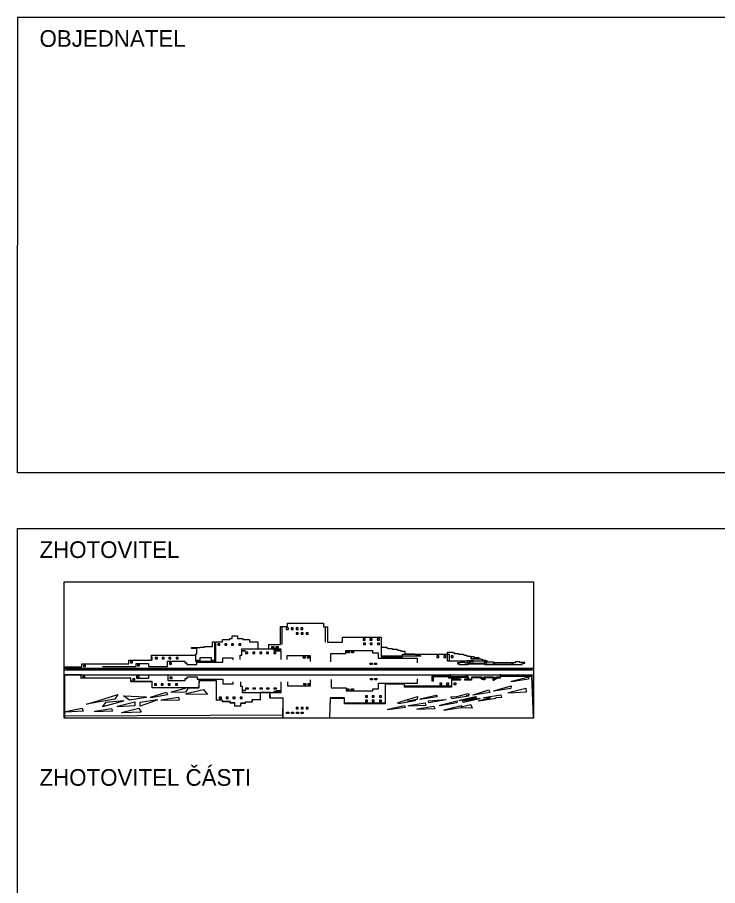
# Model space of a CAD drawing. Extents: x -740053 to -737517, y -1033516 to -1032465.
# Drawn here: x -738163 to -738131.47, y -1032574.53 to -1032535.46 of the extents above; entities that cross this region are included whole.
import ezdxf

# ---------------------------------------------------------------- set-up
doc = ezdxf.new("R2010")
doc.units = 0
doc.layers.add('promika-rozp', color=7, linetype='Continuous')

# ---------------------------------------------------------------- blocks, each defined once
blk = doc.blocks.new('onegast')
for p, q in [((22.998, 7.759), (22.998, 9.646)), ((27.598, 8.019), (27.598, 9.571)), ((9.252, 6.105), (9.252, 6.463)), ((9.309, 6.102), (9.309, 6.46)), ((6.825, 5.723), (6.825, 6.082)), ((0.046, 5.264), (49.513, 5.263)), ((0.046, 5.075), (49.427, 5.075)), ((0.278, 5.186), (49.435, 5.186)), ((0.046, 4.561), (49.435, 4.561))]:
    blk.add_line(p, q)
for points in [[(0, 14.352), (49.53, 14.352), (49.53, 0), (0, 0)], [(23.451, 9.351), (23.667, 9.351), (23.667, 9.502), (23.451, 9.502)], [(23.957, 9.351), (24.173, 9.351), (24.173, 9.502), (23.957, 9.502)], [(24.48, 9.351), (24.696, 9.351), (24.696, 9.502), (24.48, 9.502)], [(24.994, 9.351), (25.21, 9.351), (25.21, 9.502), (24.994, 9.502)], [(24.501, 8.843), (24.717, 8.843), (24.717, 8.994), (24.501, 8.994)], [(25.007, 8.843), (25.223, 8.843), (25.223, 8.994), (25.007, 8.994)], [(25.53, 8.843), (25.746, 8.843), (25.746, 8.994), (25.53, 8.994)], [(21.914, 7.53), (22.13, 7.53), (22.13, 7.378), (21.914, 7.378)], [(22.377, 7.53), (22.593, 7.53), (22.593, 7.378), (22.377, 7.378)], [(19.161, 6.799), (19.377, 6.799), (19.377, 6.95), (19.161, 6.95)], [(25.216, 6.462), (25.432, 6.462), (25.432, 6.311), (25.216, 6.311)], [(25.679, 6.462), (25.895, 6.462), (25.895, 6.311), (25.679, 6.311)], [(29.857, 7.022), (30.073, 7.022), (30.073, 6.871), (29.857, 6.871)], [(30.32, 7.022), (30.536, 7.022), (30.536, 6.871), (30.32, 6.871)], [(32.298, 5.793), (32.514, 5.793), (32.514, 5.642), (32.298, 5.642)], [(32.761, 5.793), (32.977, 5.793), (32.977, 5.642), (32.761, 5.642)], [(32.333, 4.18), (32.549, 4.18), (32.549, 4.029), (32.333, 4.029)], [(32.796, 4.18), (33.012, 4.18), (33.012, 4.029), (32.796, 4.029)], [(12.874, 2.574), (14.701, 3.028), (15.132, 2.483), (12.879, 2.512)], [(19.195, 3.182), (19.411, 3.182), (19.411, 3.031), (19.195, 3.031)], [(25.286, 3.656), (25.502, 3.656), (25.502, 3.505), (25.286, 3.505)], [(25.749, 3.656), (25.965, 3.656), (25.965, 3.505), (25.749, 3.505)], [(29.843, 3.074), (30.059, 3.074), (30.059, 2.923), (29.843, 2.923)], [(30.306, 3.074), (30.522, 3.074), (30.522, 2.923), (30.306, 2.923)], [(3.464, 1.792), (5.689, 2.483), (5.353, 1.985), (2.388, 1.451)], [(4.449, 1.687), (6.263, 1.842), (6.277, 1.778), (4.06, 1.174)], [(6.257, 2.359), (8.663, 2.239), (8.678, 2.175), (6.892, 1.886)], [(8.049, 1.674), (9.825, 1.965), (9.84, 1.9), (8.039, 1.247)], [(9.139, 2.21), (10.813, 2.729), (10.929, 2.436), (9.143, 2.148)], [(10.285, 1.911), (12.061, 2.202), (12.15, 1.899), (10.289, 1.849)], [(0.161, 0.692), (1.912, 1.059), (2.012, 0.718), (0.165, 0.63)], [(3.24, 0.71), (5.016, 1), (5.119, 0.715), (3.244, 0.648)], [(5.644, 1.239), (7.471, 1.693), (7.457, 1.283), (5.649, 1.176)], [(6.077, 0.602), (7.903, 1.057), (8.126, 0.622), (6.081, 0.54)], [(24.501, 0.974), (24.717, 0.974), (24.717, 1.125), (24.501, 1.125)], [(25.007, 0.974), (25.223, 0.974), (25.223, 1.125), (25.007, 1.125)], [(25.53, 0.974), (25.746, 0.974), (25.746, 1.125), (25.53, 1.125)], [(23.485, 0.631), (23.701, 0.631), (23.701, 0.48), (23.485, 0.48)], [(23.99, 0.631), (24.206, 0.631), (24.206, 0.48), (23.99, 0.48)], [(24.513, 0.631), (24.729, 0.631), (24.729, 0.48), (24.513, 0.48)], [(25.028, 0.631), (25.244, 0.631), (25.244, 0.48), (25.028, 0.48)]]:
    blk.add_lwpolyline(points, close=True)
for points in [[(0.046, 5.405), (1.862, 5.405), (1.862, 5.731), (6.84, 5.731), (6.84, 6.109), (9.238, 6.109), (9.238, 6.643), (13.878, 6.643), (13.878, 6.005), (16.015, 6.005), (16.015, 8.023), (16.706, 8.023), (16.706, 8.284), (17.475, 8.284), (17.475, 8.401), (17.749, 8.401), (17.749, 8.662), (18.296, 8.662), (18.296, 8.388), (18.879, 8.388), (18.879, 8.272), (19.556, 8.272), (19.556, 8.037), (20.443, 8.037), (20.443, 7.282), (21.616, 7.282), (21.616, 7.764), (22.841, 7.764), (22.841, 9.665), (23.57, 9.665), (23.57, 9.994), (27.389, 9.994), (27.389, 9.629), (27.806, 9.629), (27.806, 8.014), (29.37, 8.014), (29.37, 8.522), (33.462, 8.522), (33.462, 6.412), (35.707, 6.412), (35.707, 6.737), (40.62, 6.737), (40.62, 6.034), (44.351, 6.034), (44.351, 5.656), (48.313, 5.656)], [(31.563, 8.207), (31.779, 8.207), (31.779, 8.358), (31.563, 8.358), (31.563, 8.207)], [(32.276, 8.207), (32.493, 8.207), (32.493, 8.358), (32.276, 8.358), (32.276, 8.207)], [(33.049, 8.207), (33.265, 8.207), (33.265, 8.358), (33.049, 8.358), (33.049, 8.207)], [(14.328, 6.074), (13.905, 6.074), (13.905, 6.765), (14, 6.765), (14, 7.326), (13.453, 7.326), (13.453, 7.425), (14.378, 7.425), (14.378, 7.475), (14.825, 7.475), (14.825, 7.544), (15.233, 7.544), (15.273, 7.544), (15.68, 7.544), (15.68, 8.021), (15.879, 8.021), (15.879, 6.074), (15.571, 6.074), (15.571, 6.362), (14.328, 6.362), (14.328, 6.074)], [(16.228, 7.685), (16.444, 7.685), (16.444, 7.836), (16.228, 7.836), (16.228, 7.685)], [(16.952, 7.685), (17.168, 7.685), (17.168, 7.836), (16.952, 7.836), (16.952, 7.685)], [(17.666, 7.685), (17.882, 7.685), (17.882, 7.836), (17.666, 7.836), (17.666, 7.685)], [(18.439, 7.685), (18.655, 7.685), (18.655, 7.836), (18.439, 7.836), (18.439, 7.685)], [(31.581, 7.761), (31.797, 7.761), (31.797, 7.913), (31.581, 7.913), (31.581, 7.761)], [(32.295, 7.761), (32.511, 7.761), (32.511, 7.913), (32.295, 7.913), (32.295, 7.761)], [(33.067, 7.761), (33.284, 7.761), (33.284, 7.913), (33.067, 7.913), (33.067, 7.761)], [(37.637, 6.532), (33.482, 6.532), (33.482, 7.473), (34.037, 7.473), (34.037, 7.386), (34.193, 7.386), (34.193, 7.317), (34.616, 7.317), (34.616, 7.275), (35.159, 7.275), (35.159, 7.197), (35.257, 7.197), (35.257, 7.144), (35.467, 7.144), (35.467, 7.095), (35.652, 7.095), (35.652, 7.062), (35.94, 7.062), (35.94, 6.779), (36.976, 6.779), (36.976, 6.725), (37.165, 6.725), (37.165, 6.639), (37.502, 6.639), (37.502, 6.565), (37.637, 6.565), (37.637, 6.532)], [(18.576, 6.169), (18.576, 6.617), (18.746, 6.617), (18.746, 7.081), (19.149, 7.081), (19.149, 7.081), (18.746, 7.081), (18.746, 7.282), (22.862, 7.282), (22.862, 7.282), (22.862, 7.183), (22.396, 7.183), (22.396, 7.088), (22.871, 7.088), (22.871, 6.157)], [(19.919, 6.799), (20.135, 6.799), (20.135, 6.95), (19.919, 6.95), (19.919, 6.799)], [(20.644, 6.799), (20.86, 6.799), (20.86, 6.95), (20.644, 6.95), (20.644, 6.799)], [(21.358, 6.799), (21.574, 6.799), (21.574, 6.95), (21.358, 6.95), (21.358, 6.799)], [(22.13, 6.799), (22.346, 6.799), (22.346, 6.95), (22.13, 6.95), (22.13, 6.799)], [(22.141, 7.131), (22.357, 7.131), (22.357, 7.282), (22.141, 7.282), (22.141, 7.131)], [(23.534, 6.16), (23.534, 6.579), (25.98, 6.579), (25.98, 5.951)], [(28.148, 5.929), (28.148, 6.792), (28.724, 6.792), (28.724, 6.792), (29.741, 6.792), (29.741, 7.118), (30.144, 7.118), (30.144, 7.118), (30.97, 7.118), (30.97, 7.118), (32.543, 7.118), (32.543, 6.888), (33.138, 6.888), (33.138, 6.313), (37.246, 6.313), (37.246, 5.833)], [(39.341, 6.398), (39.557, 6.398), (39.557, 6.549), (39.341, 6.549), (39.341, 6.398)], [(40.055, 6.398), (40.271, 6.398), (40.271, 6.549), (40.055, 6.549), (40.055, 6.398)], [(40.466, 6.007), (40.466, 6.948), (41.021, 6.948), (41.021, 6.861), (41.177, 6.861), (41.177, 6.792), (41.6, 6.792), (41.6, 6.75), (42.143, 6.75), (42.143, 6.672), (42.241, 6.672), (42.241, 6.619), (42.451, 6.619), (42.451, 6.57), (42.636, 6.57), (42.636, 6.537), (42.924, 6.537), (42.924, 6.254), (43.96, 6.254), (43.96, 6.2), (44.149, 6.2), (44.149, 6.114), (44.486, 6.114), (44.486, 6.04), (44.622, 6.04), (44.622, 6.007), (40.466, 6.007)], [(44.622, 6.007), (40.466, 6.007), (40.466, 6.948), (41.021, 6.948), (41.021, 6.861), (41.177, 6.861), (41.177, 6.792), (41.6, 6.792), (41.6, 6.75), (42.143, 6.75), (42.143, 6.672), (42.241, 6.672), (42.241, 6.619), (42.451, 6.619), (42.451, 6.57), (42.636, 6.57), (42.636, 6.537), (42.924, 6.537), (42.924, 6.254), (43.96, 6.254), (43.96, 6.2), (44.149, 6.2), (44.149, 6.114), (44.486, 6.114), (44.486, 6.04), (44.622, 6.04), (44.622, 6.007)], [(40.827, 6.398), (41.043, 6.398), (41.043, 6.549), (40.827, 6.549), (40.827, 6.398)], [(42.958, 6.466), (42.958, 6.276), (43.791, 6.276), (43.791, 6.348), (43.516, 6.348), (43.516, 6.365), (43.342, 6.365), (43.342, 6.413), (43.192, 6.413), (43.192, 6.466), (42.958, 6.466)], [(43.192, 6.466), (42.958, 6.466), (42.958, 6.276), (43.791, 6.276), (43.791, 6.348), (43.516, 6.348), (43.516, 6.365), (43.342, 6.365), (43.342, 6.413), (43.192, 6.413), (43.192, 6.466)], [(2.06, 5.439), (2.276, 5.439), (2.276, 5.591), (2.06, 5.591), (2.06, 5.439)], [(4.051, 5.42), (7.596, 5.42), (7.596, 5.765), (8.897, 5.765), (8.897, 5.42), (10.933, 5.42), (10.933, 6.01), (12.761, 6.01), (12.761, 5.826), (12.957, 5.826), (12.957, 5.643), (14, 5.643), (14, 5.888), (16.736, 5.888), (16.736, 6.366), (17.815, 6.366), (17.815, 6.145)], [(7.024, 5.813), (7.24, 5.813), (7.24, 5.964), (7.024, 5.964), (7.024, 5.813)], [(7.749, 5.505), (7.965, 5.505), (7.965, 5.656), (7.749, 5.656), (7.749, 5.505)], [(9.628, 6.243), (9.844, 6.243), (9.844, 6.394), (9.628, 6.394), (9.628, 6.243)], [(10.353, 6.243), (10.569, 6.243), (10.569, 6.394), (10.353, 6.394), (10.353, 6.243)], [(11.067, 6.243), (11.283, 6.243), (11.283, 6.394), (11.067, 6.394), (11.067, 6.243)], [(11.131, 5.681), (11.348, 5.681), (11.348, 5.832), (11.131, 5.832), (11.131, 5.681)], [(11.839, 6.243), (12.055, 6.243), (12.055, 6.394), (11.839, 6.394), (11.839, 6.243)], [(41.512, 5.831), (41.512, 5.707), (41.669, 5.707), (41.669, 5.636), (42.598, 5.636), (42.598, 5.694), (42.709, 5.694), (42.709, 5.727), (44.282, 5.727), (44.282, 5.811), (44.431, 5.811), (44.431, 5.844), (44.516, 5.844), (44.516, 5.681), (45.309, 5.681), (45.309, 5.74), (45.433, 5.74), (45.433, 5.779), (45.491, 5.779), (45.491, 5.805), (47.253, 5.805), (47.253, 5.707), (47.396, 5.707), (47.396, 5.649), (48.254, 5.649), (48.254, 5.727), (48.443, 5.727), (48.443, 5.785), (48.599, 5.785), (48.599, 5.87), (48.098, 5.87), (48.098, 5.922), (47.578, 5.922), (47.578, 5.831), (45.335, 5.831), (45.335, 5.902), (44.425, 5.902), (44.425, 5.772), (44.282, 5.772), (44.282, 5.746), (42.702, 5.746), (42.702, 5.811), (42.826, 5.811), (42.826, 5.967), (43.196, 5.967), (43.196, 6.019), (42.546, 6.019), (42.546, 5.863), (42.683, 5.863), (42.683, 5.798), (42.332, 5.798), (42.332, 5.87), (41.838, 5.87), (41.838, 5.824), (41.512, 5.831)], [(44.282, 5.727), (44.282, 5.746), (42.702, 5.746), (42.702, 5.811), (42.826, 5.811), (42.826, 5.967), (43.196, 5.967), (43.196, 6.019), (42.546, 6.019), (42.546, 5.863), (42.683, 5.863), (42.683, 5.798), (42.332, 5.798), (42.332, 5.87), (41.838, 5.87), (41.838, 5.824), (41.512, 5.831), (41.512, 5.707), (41.669, 5.707), (41.669, 5.636), (42.598, 5.636), (42.598, 5.694), (42.709, 5.694), (42.709, 5.727), (44.282, 5.727)], [(44.425, 5.772), (44.425, 5.811), (44.282, 5.811), (44.282, 5.772), (44.425, 5.772)], [(44.425, 5.902), (44.425, 5.811), (44.431, 5.811), (44.431, 5.844), (44.516, 5.844), (44.516, 5.681), (45.309, 5.681), (45.309, 5.74), (45.433, 5.74), (45.433, 5.779), (45.491, 5.779), (45.491, 5.805), (47.253, 5.805), (47.253, 5.707), (47.396, 5.707), (47.396, 5.649), (48.254, 5.649), (48.254, 5.727), (48.443, 5.727), (48.443, 5.785), (48.599, 5.785), (48.599, 5.87), (48.098, 5.87), (48.098, 5.922), (47.578, 5.922), (47.578, 5.831), (45.335, 5.831), (45.335, 5.902), (44.425, 5.902)], [(0.036, 4.579), (0.065, 0.028), (23.119, 0.038), (23.133, 2.114), (21.714, 2.114), (21.714, 2.699), (20.694, 2.699), (20.694, 1.928), (19.819, 1.928), (19.819, 1.69), (19.103, 1.69), (19.103, 1.544), (18.625, 1.544), (18.625, 1.266), (18.029, 1.266), (18.029, 1.57), (17.525, 1.57), (17.525, 1.716), (16.716, 1.716), (16.716, 1.902), (16.093, 1.902), (16.093, 3.915), (14.237, 3.915), (14.237, 3.187), (9.292, 3.187), (9.292, 3.849), (7.039, 3.849), (7.039, 4.233), (1.802, 4.196), (1.811, 4.57), (0.036, 4.579)], [(0.02, 0.014), (23.093, 0.002), (23.125, 2.114), (22.3, 2.114), (21.766, 2.106), (21.766, 2.114), (21.714, 2.114), (21.714, 2.69), (20.694, 2.699), (20.694, 2.513), (20.708, 1.897), (19.841, 1.924), (19.841, 1.714), (19.819, 1.714), (19.819, 1.69), (19.163, 1.69), (19.103, 1.687), (19.103, 1.544), (18.635, 1.544), (18.625, 1.386), (18.625, 1.266), (18.256, 1.266), (18.026, 1.258), (18.017, 1.57), (17.525, 1.57), (17.525, 1.716), (16.716, 1.716), (16.716, 1.896), (16.101, 1.86), (16.101, 1.902), (16.093, 1.902), (16.093, 2.719), (16.083, 3.915), (14.514, 3.915), (14.249, 3.911), (14.237, 3.714), (14.237, 3.187), (14.206, 3.187), (14.203, 3.146), (13.089, 3.156), (12.812, 2.735), (11.338, 2.693), (11.334, 2.755), (12.803, 3.159), (9.776, 3.187), (9.292, 3.187), (9.292, 3.191), (9.287, 3.191), (9.292, 3.593), (9.292, 3.82), (7.066, 3.831), (7.065, 3.849), (7.039, 3.849), (7.039, 4.196), (2.893, 4.204), (2.028, 4.198), (1.802, 4.187), (1.803, 4.196), (1.802, 4.196), (1.81, 4.518), (0.042, 4.506), (0.02, 0.014)], [(0.042, 4.506), (0.03, 0.238), (23.125, 0.347), (23.125, 2.125), (21.766, 2.106), (21.748, 2.69), (20.689, 2.699), (20.708, 1.897), (19.841, 1.924), (19.841, 1.714), (19.093, 1.687), (19.093, 1.559), (18.637, 1.568), (18.619, 1.277), (18.026, 1.258), (18.017, 1.605), (17.542, 1.596), (17.542, 1.769), (16.721, 1.751), (16.73, 1.897), (16.101, 1.86), (16.083, 3.939), (14.249, 3.911), (14.203, 3.146), (9.287, 3.191), (9.296, 3.82), (7.066, 3.831), (7.048, 4.196), (2.185, 4.205), (1.802, 4.187), (1.821, 4.518), (0.042, 4.506)], [(1.994, 4.298), (2.21, 4.298), (2.21, 4.449), (1.994, 4.449), (1.994, 4.298)], [(4.084, 4.561), (7.63, 4.561), (7.63, 4.216), (8.93, 4.216), (8.93, 4.561), (10.967, 4.561), (10.967, 3.971), (12.794, 3.971), (12.794, 4.155), (12.991, 4.155), (12.991, 4.339), (14.034, 4.339), (14.034, 4.094), (16.769, 4.094), (16.769, 3.616), (17.849, 3.616), (17.849, 3.836)], [(7.243, 3.99), (7.46, 3.99), (7.46, 4.142), (7.243, 4.142), (7.243, 3.99)], [(7.727, 4.32), (7.943, 4.32), (7.943, 4.471), (7.727, 4.471), (7.727, 4.32)], [(11.175, 4.166), (11.391, 4.166), (11.391, 4.317), (11.175, 4.317), (11.175, 4.166)], [(18.61, 3.813), (18.61, 3.364), (18.78, 3.364), (18.78, 2.9), (19.182, 2.9), (19.182, 2.9), (18.78, 2.9), (18.78, 2.699), (22.895, 2.699), (22.895, 2.699), (22.895, 2.799), (22.429, 2.799), (22.429, 2.894), (22.904, 2.894), (22.904, 3.824)], [(23.568, 3.821), (23.568, 3.403), (26.014, 3.403), (26.014, 4.03)], [(28.067, 2.05), (27.99, 0.054), (49.512, 0.016), (49.361, 4.382), (46.076, 4.382), (46.076, 4.478), (46.005, 4.478), (46.005, 4.215), (45.632, 4.215), (45.632, 4.138), (45.529, 4.138), (45.529, 4.054), (45.349, 4.054), (45.349, 3.945), (45.259, 3.945), (45.259, 4.099), (45.439, 4.054), (45.439, 4.129), (45.439, 4.133), (45.471, 4.133), (45.471, 4.178), (45.282, 4.178), (45.282, 4.224), (44.334, 4.224), (44.334, 4.182), (44.184, 4.182), (44.184, 4.122), (44.287, 4.122), (44.287, 4.084), (44.394, 4.084), (44.394, 4.026), (44.258, 4.026), (44.258, 4.073), (44.068, 4.073), (44.068, 4.127), (44.012, 4.127), (44.012, 4.173), (44.086, 4.173), (44.086, 4.227), (42.971, 4.227), (42.971, 3.984), (42.289, 3.984), (42.289, 4.035), (42.5, 4.035), (42.5, 4.084), (42.652, 4.084), (42.652, 4.131), (42.701, 4.131), (42.701, 4.178), (42.514, 4.178), (42.514, 4.235), (42.596, 4.235), (42.596, 4.367), (42.482, 4.367), (42.482, 4.433), (42.389, 4.433), (42.389, 4.269), (40.819, 4.269), (40.819, 4.456), (40.717, 4.456), (40.717, 4.402), (40.569, 4.402), (40.569, 4.429), (38.993, 4.429), (38.993, 4.376), (38.881, 4.376), (38.881, 4.427), (38.792, 4.427), (38.792, 3.942), (38.993, 3.942), (38.993, 4.374), (40.564, 4.374), (40.564, 4.225), (41.633, 4.225), (41.633, 4.187), (41.484, 4.187), (41.484, 4.078), (41.635, 4.078), (41.635, 4.029), (41.831, 4.029), (41.831, 3.98), (40.874, 3.98), (40.874, 3.262), (35.926, 3.262), (35.926, 3.569), (33.862, 3.569), (33.862, 1.483), (29.594, 1.483), (29.594, 2.051), (28.067, 2.05)], [(28.067, 2.141), (27.991, 0.053), (49.525, -0.002), (49.509, 4.521), (46.076, 4.473), (46.076, 4.57), (46.005, 4.57), (46.005, 4.306), (45.632, 4.306), (45.632, 4.229), (45.529, 4.229), (45.529, 4.146), (45.439, 4.146), (45.349, 4.146), (45.349, 4.036), (45.259, 4.036), (45.259, 4.191), (45.439, 4.146), (45.439, 4.22), (45.439, 4.224), (45.471, 4.224), (45.471, 4.269), (45.282, 4.269), (45.282, 4.316), (44.334, 4.316), (44.334, 4.273), (44.184, 4.273), (44.184, 4.213), (44.287, 4.213), (44.287, 4.176), (44.394, 4.176), (44.394, 4.118), (44.258, 4.118), (44.258, 4.164), (44.068, 4.164), (44.068, 4.218), (44.012, 4.218), (44.012, 4.265), (44.086, 4.265), (44.086, 4.318), (42.971, 4.318), (42.971, 4.076), (42.289, 4.076), (42.289, 4.126), (42.5, 4.126), (42.5, 4.175), (42.652, 4.175), (42.652, 4.222), (42.701, 4.222), (42.701, 4.269), (42.514, 4.269), (42.514, 4.327), (42.596, 4.327), (42.596, 4.458), (42.482, 4.458), (42.482, 4.525), (42.389, 4.525), (42.389, 4.36), (40.819, 4.36), (40.819, 4.547), (40.717, 4.547), (40.717, 4.494), (40.569, 4.494), (40.569, 4.52), (38.993, 4.52), (38.993, 4.465), (40.564, 4.465), (40.564, 4.316), (41.633, 4.316), (41.633, 4.278), (41.484, 4.278), (41.484, 4.169), (41.635, 4.169), (41.635, 4.12), (41.831, 4.12), (41.831, 4.071), (40.874, 4.071), (40.874, 3.353), (35.926, 3.353), (35.926, 3.66), (33.862, 3.66), (33.862, 1.575), (29.594, 1.575), (29.594, 2.142), (28.067, 2.141)], [(28.182, 4.052), (28.182, 3.189), (28.757, 3.189), (28.757, 3.189), (29.775, 3.189), (29.775, 2.863), (30.178, 2.863), (30.178, 2.863), (31.003, 2.863), (31.003, 2.863), (32.577, 2.863), (32.577, 3.093), (33.172, 3.093), (33.172, 3.669), (37.279, 3.669), (37.279, 4.148)], [(39.65, 3.525), (39.866, 3.525), (39.866, 3.677), (39.65, 3.677), (39.65, 3.525)], [(40.364, 3.525), (40.58, 3.525), (40.58, 3.677), (40.364, 3.677), (40.364, 3.525)], [(41.136, 3.525), (41.352, 3.525), (41.352, 3.677), (41.136, 3.677), (41.136, 3.525)], [(49.007, 4.105), (47.221, 3.817), (47.216, 3.879), (49.043, 4.334), (49.007, 4.105)], [(9.536, 3.464), (9.752, 3.464), (9.752, 3.615), (9.536, 3.615), (9.536, 3.464)], [(10.26, 3.464), (10.476, 3.464), (10.476, 3.615), (10.26, 3.615), (10.26, 3.464)], [(10.974, 3.464), (11.19, 3.464), (11.19, 3.615), (10.974, 3.615), (10.974, 3.464)], [(11.746, 3.464), (11.963, 3.464), (11.963, 3.615), (11.746, 3.615), (11.746, 3.464)], [(15.132, 2.483), (12.879, 2.512), (12.874, 2.574), (14.701, 3.028), (15.132, 2.483)], [(19.195, 3.031), (19.195, 3.182), (19.411, 3.182), (19.411, 3.031), (19.195, 3.031)], [(20.169, 3.031), (19.953, 3.031), (19.953, 3.182), (20.169, 3.182), (20.169, 3.031)], [(20.893, 3.031), (20.677, 3.031), (20.677, 3.182), (20.893, 3.182), (20.893, 3.031)], [(21.607, 3.031), (21.391, 3.031), (21.391, 3.182), (21.607, 3.182), (21.607, 3.031)], [(22.38, 3.031), (22.164, 3.031), (22.164, 3.182), (22.38, 3.182), (22.38, 3.031)], [(22.39, 2.699), (22.174, 2.699), (22.174, 2.85), (22.39, 2.85), (22.39, 2.699)], [(44.937, 2.689), (43.151, 2.401), (43.147, 2.463), (44.821, 2.982), (44.937, 2.689)], [(47.132, 3.109), (45.346, 2.82), (45.342, 2.882), (47.162, 3.382), (47.132, 3.109)], [(48.753, 2.715), (46.887, 2.639), (46.882, 2.701), (48.709, 3.155), (48.753, 2.715)], [(2.388, 1.451), (3.464, 1.792), (5.689, 2.483), (5.353, 1.985), (2.388, 1.451)], [(4.06, 1.174), (4.449, 1.687), (6.263, 1.842), (6.277, 1.778), (4.06, 1.174)], [(6.892, 1.886), (6.257, 2.359), (8.663, 2.239), (8.678, 2.175), (6.892, 1.886)], [(8.039, 1.247), (8.049, 1.674), (9.825, 1.965), (9.84, 1.9), (8.039, 1.247)], [(9.143, 2.148), (9.139, 2.21), (10.813, 2.729), (10.929, 2.436), (9.143, 2.148)], [(10.289, 1.849), (10.285, 1.911), (12.061, 2.202), (12.15, 1.899), (10.289, 1.849)], [(16.383, 2.065), (16.599, 2.065), (16.599, 2.216), (16.383, 2.216), (16.383, 2.065)], [(17.107, 2.065), (17.324, 2.065), (17.324, 2.216), (17.107, 2.216), (17.107, 2.065)], [(17.821, 2.065), (18.037, 2.065), (18.037, 2.216), (17.821, 2.216), (17.821, 2.065)], [(18.594, 2.065), (18.81, 2.065), (18.81, 2.216), (18.594, 2.216), (18.594, 2.065)], [(31.804, 2.197), (32.02, 2.197), (32.02, 2.348), (31.804, 2.348), (31.804, 2.197)], [(31.804, 1.752), (32.02, 1.752), (32.02, 1.903), (31.804, 1.903), (31.804, 1.752)], [(32.518, 2.197), (32.734, 2.197), (32.734, 2.348), (32.518, 2.348), (32.518, 2.197)], [(32.518, 1.752), (32.734, 1.752), (32.734, 1.903), (32.518, 1.903), (32.518, 1.752)], [(33.29, 2.197), (33.506, 2.197), (33.506, 2.348), (33.29, 2.348), (33.29, 2.197)], [(33.29, 1.752), (33.506, 1.752), (33.506, 1.903), (33.29, 1.903), (33.29, 1.752)], [(37.045, 1.826), (35.275, 1.483), (35.212, 1.656), (35.458, 1.687), (35.456, 1.725), (37.304, 2.273), (37.246, 1.951), (36.232, 1.787), (37.03, 1.89), (37.045, 1.826)], [(39.361, 2.237), (37.575, 1.949), (37.57, 2.011), (39.263, 2.411), (39.361, 2.237)], [(40.285, 1.905), (38.499, 1.617), (38.457, 1.814), (40.271, 1.97), (40.285, 1.905)], [(42.686, 2.302), (40.9, 2.014), (40.791, 2.246), (41.431, 2.287), (42.647, 2.574), (42.745, 2.401), (42.436, 2.351), (42.671, 2.366), (42.686, 2.302)], [(43.522, 2.115), (41.736, 1.826), (41.732, 1.888), (43.425, 2.288), (43.522, 2.115)], [(43.848, 2.028), (42.108, 1.637), (42.057, 1.801), (43.833, 2.092), (43.848, 2.028)], [(45.555, 2.06), (43.769, 1.772), (43.765, 1.834), (44.98, 2.121), (44.297, 2.102), (44.293, 2.164), (46.069, 2.455), (46.158, 2.152), (45.513, 2.135), (45.555, 2.06)], [(0.165, 0.63), (0.161, 0.692), (1.912, 1.059), (2.012, 0.718), (0.165, 0.63)], [(3.244, 0.648), (3.24, 0.71), (5.016, 1), (5.119, 0.715), (3.244, 0.648)], [(5.649, 1.176), (5.644, 1.239), (7.471, 1.693), (7.457, 1.283), (5.649, 1.176)], [(6.081, 0.54), (6.077, 0.602), (7.903, 1.057), (8.126, 0.622), (6.081, 0.54)], [(35.996, 1.11), (34.173, 0.883), (34.169, 0.945), (35.92, 1.312), (35.996, 1.11)], [(38.172, 1.324), (36.328, 1.254), (36.324, 1.316), (38.1, 1.607), (38.172, 1.324)], [(39.127, 0.968), (37.252, 0.901), (37.248, 0.963), (39.024, 1.253), (39.127, 0.968)], [(41.443, 1.592), (39.657, 1.304), (39.653, 1.366), (41.479, 1.82), (41.443, 1.592)], [(41.875, 1.082), (40.089, 0.793), (40.085, 0.855), (41.911, 1.31), (41.894, 1.2), (42.92, 1.442), (43.064, 1.042), (41.875, 1.085), (41.875, 1.082)]]:
    blk.add_lwpolyline(points)

msp = doc.modelspace()

# ---------------------------------------------------------------- linework, layer by layer
at = {"layer": 'promika-rozp'}
for points in [[(-738072.999, -1032545.713), (-738072.999, -1032535.463), (-738162.999, -1032535.463), (-738162.999, -1032545.713)], [(-738072.999, -1032545.713), (-738072.999, -1032555.963), (-738162.999, -1032555.963), (-738162.999, -1032545.713)], [(-738162.999, -1032578.963), (-738162.999, -1032558.463), (-738072.999, -1032558.463), (-738072.999, -1032578.963)]]:
    msp.add_lwpolyline(points, dxfattribs=at)

# ---------------------------------------------------------------- block references
at = {"xscale": 0.4267458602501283, "yscale": 0.4267458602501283}
msp.add_blockref('onegast', (-738160.898, -1032566.992), dxfattribs=at)

# ---------------------------------------------------------------- texts
at = {"layer": 'promika-rozp'}
for s, p in [('OBJEDNATEL', (-738162.001, -1032536.789)), ('ZHOTOVITEL', (-738162.001, -1032559.789)), ('ZHOTOVITEL ČÁSTI', (-738162.001, -1032570.039))]:
    msp.add_text(s, height=0.75, dxfattribs=at).set_placement(p)

doc.saveas('drawing.dxf')
